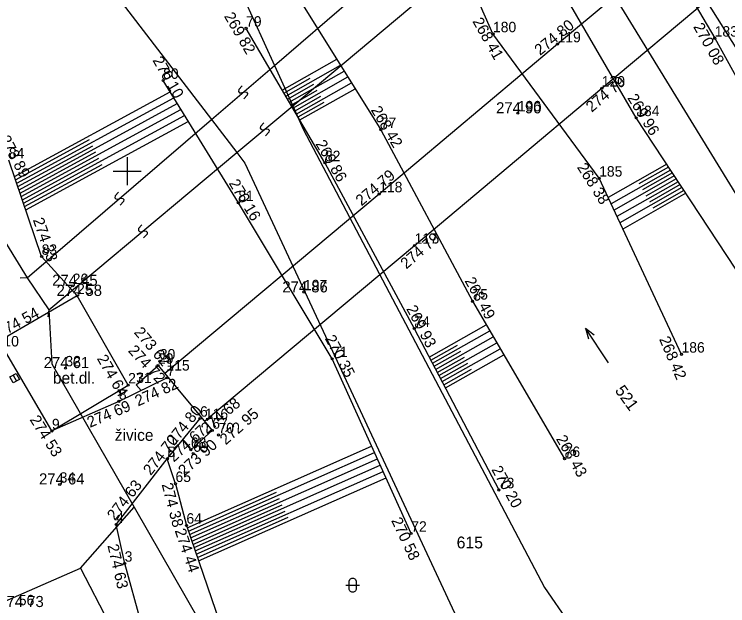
# Model space of a CAD drawing. Extents: x -492379 to -491966, y -1126153 to -1125860.
# Drawn here: x -492184.88 to -492154.06, y -1126038.78 to -1126013.22 of the extents above; entities that cross this region are included whole.
import ezdxf

# ---------------------------------------------------------------- set-up
doc = ezdxf.new("R2010")
doc.units = 0
for name, color, linetype in [('body', 7, 'Continuous'), ('hrana svahu', 7, 'Continuous'), ('kanalizace', 7, 'Continuous'), ('katastrální mapa', 7, 'Continuous'), ('ostatní objekty', 7, 'Continuous'), ('podrobný výškový bod', 7, 'Continuous'), ('popis ploch', 7, 'Continuous'), ('rozhraní ploch', 7, 'Continuous'), ('síť', 7, 'Continuous'), ('vodstvo', 7, 'Continuous'), ('výšky', 7, 'Continuous'), ('čísla bodů', 7, 'Continuous'), ('šrafy', 7, 'Continuous')]:
    doc.layers.add(name, color=color, linetype=linetype)

msp = doc.modelspace()

# ---------------------------------------------------------------- linework, layer by layer
at = {"layer": 'body'}
for p, q in [((-492174.865, -1126013.831), (-492174.865, -1126013.831)), ((-492164.201, -1126014.074), (-492164.201, -1126014.074)), ((-492154.625, -1126014.262), (-492154.625, -1126014.262)), ((-492161.411, -1126014.509), (-492161.411, -1126014.509)), ((-492178.448, -1126016.087), (-492178.448, -1126016.087)), ((-492159.503, -1126016.42), (-492159.503, -1126016.42)), ((-492163.128, -1126017.492), (-492163.128, -1126017.492)), ((-492158.013, -1126017.698), (-492158.013, -1126017.698)), ((-492169.047, -1126018.211), (-492169.047, -1126018.211)), ((-492171.458, -1126019.645), (-492171.458, -1126019.645)), ((-492159.615, -1126020.311), (-492159.615, -1126020.311)), ((-492169.116, -1126020.989), (-492169.116, -1126020.989)), ((-492175.199, -1126021.368), (-492175.199, -1126021.368)), ((-492167.589, -1126023.215), (-492167.589, -1126023.215)), ((-492183.695, -1126023.691), (-492183.695, -1126023.691)), ((-492182.354, -1126024.953), (-492182.354, -1126024.953)), ((-492172.363, -1126025.222), (-492172.363, -1126025.222)), ((-492182.164, -1126025.391), (-492182.164, -1126025.391)), ((-492165.087, -1126025.624), (-492165.087, -1126025.624)), ((-492167.599, -1126026.803), (-492167.599, -1126026.803)), ((-492171.148, -1126028.112), (-492171.148, -1126028.112)), ((-492156.058, -1126027.916), (-492156.058, -1126027.916)), ((-492178.667, -1126028.396), (-492178.667, -1126028.396)), ((-492178.591, -1126028.212), (-492178.591, -1126028.212)), ((-492182.668, -1126028.51), (-492182.668, -1126028.51)), ((-492178.305, -1126028.692), (-492178.305, -1126028.692)), ((-492178.279, -1126028.929), (-492178.279, -1126028.929)), ((-492179.957, -1126029.249), (-492179.957, -1126029.249)), ((-492179.61, -1126029.228), (-492179.61, -1126029.228)), ((-492180.359, -1126029.948), (-492180.359, -1126029.948)), ((-492176.853, -1126030.685), (-492176.853, -1126030.685)), ((-492176.644, -1126030.789), (-492176.644, -1126030.789)), ((-492176.325, -1126031.204), (-492176.325, -1126031.204)), ((-492183.251, -1126031.227), (-492183.251, -1126031.227)), ((-492176.057, -1126031.401), (-492176.057, -1126031.401)), ((-492177.249, -1126032.036), (-492177.249, -1126032.036)), ((-492178.267, -1126032.429), (-492178.267, -1126032.429)), ((-492177.149, -1126032.202), (-492177.149, -1126032.202)), ((-492161.105, -1126032.425), (-492161.105, -1126032.425)), ((-492182.916, -1126033.537), (-492182.916, -1126033.537)), ((-492177.915, -1126033.506), (-492177.915, -1126033.506)), ((-492163.945, -1126033.776), (-492163.945, -1126033.776)), ((-492180.477, -1126035.272), (-492180.477, -1126035.272)), ((-492177.441, -1126035.306), (-492177.441, -1126035.306)), ((-492167.73, -1126035.654), (-492167.73, -1126035.654)), ((-492180.108, -1126036.95), (-492180.108, -1126036.95))]:
    msp.add_line(p, q, dxfattribs=at)
at = {"layer": 'hrana svahu'}
for p, q in [((-492157.632, -1126009.099), (-492154.625, -1126014.262)), ((-492158.013, -1126017.698), (-492161.461, -1126011.771)), ((-492171.458, -1126019.645), (-492174.865, -1126013.831)), ((-492154.625, -1126014.262), (-492150.476, -1126021.763)), ((-492175.199, -1126021.368), (-492178.448, -1126016.087)), ((-492153.329, -1126024.834), (-492158.013, -1126017.698)), ((-492183.695, -1126023.691), (-492185.109, -1126019.52)), ((-492171.458, -1126019.645), (-492167.599, -1126026.803)), ((-492171.148, -1126028.112), (-492175.199, -1126021.368)), ((-492183.695, -1126023.691), (-492182.164, -1126025.391)), ((-492167.599, -1126026.803), (-492163.945, -1126033.776)), ((-492167.73, -1126035.654), (-492171.148, -1126028.112)), ((-492177.915, -1126033.506), (-492178.267, -1126032.429)), ((-492177.915, -1126033.506), (-492177.441, -1126035.306)), ((-492177.441, -1126035.306), (-492175.63, -1126040.598))]:
    msp.add_line(p, q, dxfattribs=at)
at = {"layer": 'kanalizace'}
msp.add_line((-492184.929, -1126028.814), (-492184.787, -1126029.078), dxfattribs=at)
msp.add_lwpolyline([(-492184.797, -1126028.743), (-492184.655, -1126029.008), (-492184.92, -1126029.149), (-492185.062, -1126028.885)], close=True, dxfattribs=at)
at = {"layer": 'katastrální mapa'}
for p, q in [((-492198.1, -1125989.34), (-492176.36, -1126017.77)), ((-492196.25, -1126005.33), (-492184.32, -1126024.61)), ((-492159.27, -1126005.79), (-492138.809, -1126038.508)), ((-492173.64, -1126015.43), (-492162.81, -1126006.12)), ((-492172.85, -1126017.18), (-492161.74, -1126007.87)), ((-492161.74, -1126007.87), (-492142.973, -1126038.587)), ((-492176.09, -1126010.03), (-492173.64, -1126015.43)), ((-492176.36, -1126017.77), (-492173.64, -1126015.43)), ((-492173.64, -1126015.43), (-492172.85, -1126017.18)), ((-492175.04, -1126016.32), (-492175.18, -1126016.48)), ((-492175.18, -1126016.48), (-492175.19, -1126016.56)), ((-492175.19, -1126016.56), (-492175.15, -1126016.61)), ((-492175.15, -1126016.61), (-492175.07, -1126016.62)), ((-492175.07, -1126016.62), (-492174.93, -1126016.58)), ((-492174.82, -1126016.72), (-492174.96, -1126016.88)), ((-492174.93, -1126016.58), (-492174.85, -1126016.59)), ((-492174.85, -1126016.59), (-492174.81, -1126016.64)), ((-492174.81, -1126016.64), (-492174.82, -1126016.72)), ((-492175.27, -1126019.2), (-492172.85, -1126017.18)), ((-492172.85, -1126017.18), (-492172.4, -1126018.18)), ((-492184.32, -1126024.61), (-492176.36, -1126017.77)), ((-492176.36, -1126017.77), (-492175.27, -1126019.2)), ((-492174.1, -1126017.91), (-492174.24, -1126018.07)), ((-492174.24, -1126018.07), (-492174.25, -1126018.15)), ((-492174.25, -1126018.15), (-492174.21, -1126018.2)), ((-492174.21, -1126018.2), (-492174.13, -1126018.21)), ((-492174.13, -1126018.21), (-492173.99, -1126018.17)), ((-492173.99, -1126018.17), (-492173.91, -1126018.18)), ((-492173.91, -1126018.18), (-492173.87, -1126018.23)), ((-492173.87, -1126018.23), (-492173.88, -1126018.31)), ((-492172.4, -1126018.18), (-492161.97, -1126037.99)), ((-492173.88, -1126018.31), (-492174.02, -1126018.47)), ((-492183.38, -1126026), (-492175.27, -1126019.2)), ((-492175.27, -1126019.2), (-492174.92, -1126019.66)), ((-492174.92, -1126019.66), (-492165.34, -1126040.21)), ((-492180.38, -1126020.91), (-492180.52, -1126021.07)), ((-492180.52, -1126021.07), (-492180.53, -1126021.15)), ((-492180.53, -1126021.15), (-492180.49, -1126021.2)), ((-492180.49, -1126021.2), (-492180.41, -1126021.21)), ((-492180.41, -1126021.21), (-492180.27, -1126021.17)), ((-492180.16, -1126021.31), (-492180.3, -1126021.47)), ((-492180.27, -1126021.17), (-492180.19, -1126021.18)), ((-492180.19, -1126021.18), (-492180.15, -1126021.23)), ((-492180.15, -1126021.23), (-492180.16, -1126021.31)), ((-492179.36, -1126022.32), (-492179.51, -1126022.48)), ((-492179.51, -1126022.48), (-492179.51, -1126022.56)), ((-492179.51, -1126022.56), (-492179.47, -1126022.61)), ((-492179.39, -1126022.62), (-492179.26, -1126022.58)), ((-492179.26, -1126022.58), (-492179.18, -1126022.59)), ((-492179.47, -1126022.61), (-492179.39, -1126022.62)), ((-492179.14, -1126022.72), (-492179.29, -1126022.88)), ((-492179.18, -1126022.59), (-492179.14, -1126022.64)), ((-492179.14, -1126022.64), (-492179.14, -1126022.72)), ((-492184.32, -1126024.61), (-492184.62, -1126024.63)), ((-492184.32, -1126024.61), (-492183.38, -1126026)), ((-492183.38, -1126026), (-492183.42, -1126026.29)), ((-492183.38, -1126026), (-492183.25, -1126028.33)), ((-492159.209, -1126028.283), (-492160.205, -1126026.785)), ((-492160.205, -1126026.785), (-492160.078, -1126027.242)), ((-492160.205, -1126026.785), (-492159.833, -1126027.077)), ((-492183.25, -1126028.33), (-492179.7, -1126034.52)), ((-492182.01, -1126037.16), (-492179.7, -1126034.52)), ((-492179.7, -1126034.52), (-492160.79, -1126067.45)), ((-492191.74, -1126041.4), (-492182.01, -1126037.16)), ((-492182.01, -1126037.16), (-492168.25, -1126063.67)), ((-492170.41, -1126037.71), (-492170.38, -1126037.65)), ((-492170.38, -1126037.65), (-492170.35, -1126037.62)), ((-492170.35, -1126037.62), (-492170.29, -1126037.59)), ((-492170.29, -1126037.59), (-492170.23, -1126037.59)), ((-492170.23, -1126037.59), (-492170.17, -1126037.62)), ((-492170.17, -1126037.62), (-492170.14, -1126037.65)), ((-492170.14, -1126037.65), (-492170.11, -1126037.71)), ((-492170.56, -1126037.89), (-492169.96, -1126037.89)), ((-492170.41, -1126038.07), (-492170.41, -1126037.71)), ((-492170.11, -1126037.71), (-492170.11, -1126038.07)), ((-492161.97, -1126037.99), (-492143.79, -1126064.46)), ((-492170.38, -1126038.13), (-492170.41, -1126038.07)), ((-492170.35, -1126038.16), (-492170.38, -1126038.13)), ((-492170.29, -1126038.19), (-492170.35, -1126038.16)), ((-492170.23, -1126038.19), (-492170.29, -1126038.19)), ((-492170.17, -1126038.16), (-492170.23, -1126038.19)), ((-492170.14, -1126038.13), (-492170.17, -1126038.16)), ((-492170.11, -1126038.07), (-492170.14, -1126038.13))]:
    msp.add_line(p, q, dxfattribs=at)
at = {"layer": 'ostatní objekty'}
for p, q in [((-492150.774, -1126005.547), (-492161.411, -1126014.509)), ((-492159.503, -1126016.42), (-492148.949, -1126007.574)), ((-492161.411, -1126014.509), (-492169.116, -1126020.989)), ((-492167.589, -1126023.215), (-492159.503, -1126016.42)), ((-492169.116, -1126020.989), (-492178.373, -1126028.749)), ((-492176.66, -1126030.802), (-492167.589, -1126023.215)), ((-492179.61, -1126029.228), (-492178.667, -1126028.396)), ((-492178.667, -1126028.396), (-492176.325, -1126031.204)), ((-492179.61, -1126029.228), (-492179.4, -1126029.478)), ((-492176.325, -1126031.204), (-492177.249, -1126032.036)), ((-492177.605, -1126031.613), (-492177.249, -1126032.036))]:
    msp.add_line(p, q, dxfattribs=at)
at = {"layer": 'podrobný výškový bod'}
for centre in [(-492174.865, -1126013.831), (-492164.201, -1126014.074), (-492154.625, -1126014.262), (-492161.411, -1126014.509), (-492178.448, -1126016.087), (-492159.503, -1126016.42), (-492163.128, -1126017.492), (-492158.013, -1126017.698), (-492169.047, -1126018.211), (-492171.458, -1126019.645), (-492159.615, -1126020.311), (-492169.116, -1126020.989), (-492175.199, -1126021.368), (-492167.589, -1126023.215), (-492183.695, -1126023.691), (-492182.354, -1126024.953), (-492182.164, -1126025.391), (-492172.363, -1126025.222), (-492165.087, -1126025.624), (-492167.599, -1126026.803), (-492171.148, -1126028.112), (-492156.058, -1126027.916), (-492178.667, -1126028.396), (-492178.591, -1126028.212), (-492182.668, -1126028.51), (-492178.279, -1126028.929), (-492179.957, -1126029.249), (-492180.359, -1126029.948), (-492176.853, -1126030.685), (-492183.251, -1126031.227), (-492176.325, -1126031.204), (-492176.057, -1126031.401), (-492177.249, -1126032.036), (-492178.267, -1126032.429), (-492177.149, -1126032.202), (-492161.105, -1126032.425), (-492182.916, -1126033.537), (-492177.915, -1126033.506), (-492163.945, -1126033.776), (-492180.477, -1126035.272), (-492177.441, -1126035.306), (-492167.73, -1126035.654), (-492180.108, -1126036.95)]:
    msp.add_circle(centre, 0.045, dxfattribs=at)
at = {"layer": 'rozhraní ploch'}
for p, q in [((-492182.164, -1126025.391), (-492185.549, -1126027.345)), ((-492179.957, -1126029.249), (-492182.164, -1126025.391)), ((-492183.251, -1126031.227), (-492185.346, -1126027.649)), ((-492178.279, -1126028.929), (-492180.359, -1126029.948)), ((-492183.251, -1126031.227), (-492179.957, -1126029.249)), ((-492180.359, -1126029.948), (-492183.251, -1126031.227)), ((-492178.267, -1126032.429), (-492176.853, -1126030.685)), ((-492180.477, -1126035.272), (-492178.267, -1126032.429)), ((-492180.108, -1126036.95), (-492180.477, -1126035.272)), ((-492179.273, -1126039.927), (-492180.108, -1126036.95))]:
    msp.add_line(p, q, dxfattribs=at)
at = {"layer": 'síť'}
for p, q in [((-492180, -1126019.4), (-492180, -1126020.6)), ((-492180.6, -1126020), (-492179.4, -1126020))]:
    msp.add_line(p, q, dxfattribs=at)
at = {"layer": 'vodstvo'}
for p, q in [((-492164.201, -1126014.074), (-492166.662, -1126008.473)), ((-492172.655, -1126012.43), (-492169.047, -1126018.211)), ((-492159.615, -1126020.311), (-492164.201, -1126014.074)), ((-492169.047, -1126018.211), (-492165.087, -1126025.624)), ((-492156.058, -1126027.916), (-492159.615, -1126020.311)), ((-492165.087, -1126025.624), (-492161.105, -1126032.425))]:
    msp.add_line(p, q, dxfattribs=at)
at = {"layer": 'šrafy'}
for p, q in [((-492173.303, -1126016.496), (-492170.948, -1126015.165)), ((-492173.152, -1126016.755), (-492170.789, -1126015.42)), ((-492173, -1126017.014), (-492170.63, -1126015.675)), ((-492173.227, -1126016.625), (-492172.093, -1126015.984)), ((-492172.848, -1126017.273), (-492170.471, -1126015.93)), ((-492173.076, -1126016.884), (-492171.941, -1126016.243)), ((-492172.697, -1126017.532), (-492170.312, -1126016.184)), ((-492184.868, -1126020.232), (-492178.149, -1126016.573)), ((-492172.924, -1126017.143), (-492171.79, -1126016.503)), ((-492172.545, -1126017.79), (-492170.153, -1126016.439)), ((-492184.77, -1126020.52), (-492177.992, -1126016.829)), ((-492172.772, -1126017.402), (-492171.639, -1126016.762)), ((-492172.621, -1126017.661), (-492171.488, -1126017.021)), ((-492184.672, -1126020.808), (-492177.834, -1126017.085)), ((-492184.575, -1126021.097), (-492177.677, -1126017.341)), ((-492184.477, -1126021.385), (-492177.519, -1126017.596)), ((-492184.379, -1126021.673), (-492177.362, -1126017.852)), ((-492184.819, -1126020.376), (-492181.624, -1126018.636)), ((-492184.721, -1126020.664), (-492181.489, -1126018.904)), ((-492184.623, -1126020.952), (-492181.354, -1126019.172)), ((-492184.526, -1126021.241), (-492181.219, -1126019.44)), ((-492184.428, -1126021.529), (-492181.084, -1126019.708)), ((-492156.698, -1126019.702), (-492159.228, -1126021.139)), ((-492156.533, -1126019.953), (-492159.1, -1126021.412)), ((-492156.615, -1126019.827), (-492157.894, -1126020.554)), ((-492156.45, -1126020.079), (-492157.745, -1126020.814)), ((-492156.368, -1126020.204), (-492158.973, -1126021.684)), ((-492156.285, -1126020.33), (-492157.596, -1126021.075)), ((-492156.203, -1126020.456), (-492158.845, -1126021.957)), ((-492156.038, -1126020.707), (-492158.718, -1126022.229)), ((-492156.12, -1126020.581), (-492157.447, -1126021.335)), ((-492155.873, -1126020.958), (-492158.59, -1126022.502)), ((-492155.955, -1126020.833), (-492157.298, -1126021.595)), ((-492166.955, -1126028.032), (-492164.492, -1126026.64)), ((-492166.816, -1126028.298), (-492164.34, -1126026.899)), ((-492166.676, -1126028.564), (-492164.189, -1126027.158)), ((-492166.885, -1126028.165), (-492165.735, -1126027.515)), ((-492166.537, -1126028.829), (-492164.037, -1126027.417)), ((-492166.746, -1126028.431), (-492165.583, -1126027.774)), ((-492166.398, -1126029.095), (-492163.886, -1126027.676)), ((-492166.607, -1126028.696), (-492165.432, -1126028.033)), ((-492166.258, -1126029.361), (-492163.734, -1126027.935)), ((-492166.467, -1126028.962), (-492165.281, -1126028.292)), ((-492166.328, -1126029.228), (-492165.13, -1126028.551)), ((-492177.404, -1126035.413), (-492169.441, -1126031.879)), ((-492177.307, -1126035.698), (-492169.317, -1126032.153)), ((-492177.209, -1126035.983), (-492169.193, -1126032.426)), ((-492177.112, -1126036.268), (-492169.069, -1126032.699)), ((-492177.014, -1126036.553), (-492168.945, -1126032.972)), ((-492176.917, -1126036.838), (-492168.821, -1126033.246)), ((-492177.356, -1126035.556), (-492173.549, -1126033.867)), ((-492177.258, -1126035.841), (-492173.424, -1126034.139)), ((-492177.161, -1126036.126), (-492173.299, -1126034.412)), ((-492177.063, -1126036.41), (-492173.174, -1126034.685)), ((-492176.966, -1126036.695), (-492173.049, -1126034.958))]:
    msp.add_line(p, q, dxfattribs=at)

# ---------------------------------------------------------------- texts
at = {"layer": 'katastrální mapa'}
msp.add_text('521', height=0.51, rotation=305.881, dxfattribs=at).set_placement((-492158.955, -1126029.482))
msp.add_text('615', height=0.51, dxfattribs=at).set_placement((-492165.77, -1126036.3))
at = {"layer": 'popis ploch'}
for s, p in [('bet.dl.', (-492183.207, -1126029.184)), ('živice', (-492180.536, -1126031.653))]:
    msp.add_text(s, height=0.5, dxfattribs=at).set_placement(p)
at = {"layer": 'výšky'}
for s, rotation, p in [('269 82', 300.2469, (-492175.83, -1126013.304)), ('268 41', 299.5607, (-492165.1, -1126013.528)), ('274 80', 39.5007, (-492162.166, -1126015.025)), ('270 08', 299.3475, (-492155.563, -1126013.759)), ('270 10', 299.9294, (-492178.919, -1126015.208)), ('274 79', 40.1281, (-492159.937, -1126017.48)), ('269 96', 301.3667, (-492158.41, -1126016.836)), ('268 42', 300.8153, (-492169.489, -1126017.357)), ('273 89', 298.1924, (-492185.522, -1126018.61)), ('269 86', 300.2536, (-492171.88, -1126018.821)), ('268 38', 302.1912, (-492160.585, -1126019.831)), ('274 79', 40.3826, (-492169.879, -1126021.528)), ('270 16', 301.1243, (-492175.625, -1126020.522)), ('274 33', 289.1415, (-492184.079, -1126022.104)), ('274 79', 40.713, (-492167.944, -1126024.254)), ('268 49', 298.7456, (-492165.437, -1126024.736)), ('274 54', 28.5451, (-492185.477, -1126027.214)), ('269 93', 297.7256, (-492167.958, -1126025.943)), ('273 62', 310.4177, (-492179.731, -1126026.978)), ('270 35', 297.864, (-492171.474, -1126027.229)), ('268 42', 293.1079, (-492157.032, -1126027.258)), ('274 72', 312.8933, (-492179.988, -1126027.78)), ('274 64', 299.5772, (-492181.322, -1126028.093)), ('274 82', 24.6497, (-492179.531, -1126030.172)), ('274 69', 23.1235, (-492181.607, -1126031.093)), ('274 68', 40.5539, (-492176.559, -1126031.381)), ('274 80', 51.1063, (-492177.972, -1126031.89)), ('272 95', 41.5117, (-492175.742, -1126031.853)), ('274 53', 302.2306, (-492184.227, -1126030.734)), ('274 67', 42.0009, (-492177.986, -1126032.596)), ('274 70', 51.5892, (-492178.981, -1126033.176)), ('268 43', 299.6467, (-492161.491, -1126031.567)), ('273 90', 41.689, (-492177.534, -1126033.2)), ('270 20', 298.9222, (-492164.28, -1126032.889)), ('274 63', 52.1283, (-492180.535, -1126035.127)), ('274 38', 284.753, (-492178.515, -1126033.534)), ('270 58', 295.3282, (-492168.607, -1126035.093)), ('274 44', 288.7897, (-492177.953, -1126035.53)), ('274 63', 283.1518, (-492180.855, -1126036.174))]:
    msp.add_text(s, height=0.48, rotation=rotation, dxfattribs=at).set_placement(p)
for s, p in [('274 90', (-492164.067, -1126017.504)), ('274 45', (-492183.24, -1126024.953)), ('274 58', (-492183.05, -1126025.391)), ('274 86', (-492173.299, -1126025.24)), ('274 61', (-492183.604, -1126028.51)), ('274 64', (-492183.807, -1126033.537)), ('274 73', (-492185.567, -1126038.835))]:
    msp.add_text(s, height=0.48, dxfattribs=at).set_placement(p)
at = {"layer": 'čísla bodů'}
for s, p in [('79', (-492174.865, -1126013.756)), ('180', (-492164.201, -1126013.999)), ('183', (-492154.625, -1126014.187)), ('119', (-492161.411, -1126014.434)), ('80', (-492178.448, -1126016.012)), ('120', (-492159.503, -1126016.345)), ('196', (-492163.128, -1126017.417)), ('184', (-492158.013, -1126017.623)), ('77', (-492169.047, -1126018.136)), ('84', (-492185.109, -1126019.445)), ('82', (-492171.458, -1126019.57)), ('185', (-492159.615, -1126020.236)), ('118', (-492169.116, -1126020.914)), ('81', (-492175.199, -1126021.293)), ('117', (-492167.589, -1126023.14)), ('83', (-492183.695, -1126023.616)), ('26', (-492182.354, -1126024.878)), ('197', (-492172.363, -1126025.147)), ('25', (-492182.164, -1126025.316)), ('75', (-492165.087, -1126025.549)), ('74', (-492167.599, -1126026.728)), ('10', (-492185.346, -1126027.574)), ('186', (-492156.058, -1126027.841)), ('30', (-492178.591, -1126028.137)), ('71', (-492171.148, -1126028.037)), ('32', (-492182.668, -1126028.435)), ('29', (-492178.667, -1126028.321)), ('115', (-492178.305, -1126028.617)), ('7', (-492178.279, -1126028.854)), ('27', (-492179.957, -1126029.174)), ('31', (-492179.61, -1126029.153)), ('8', (-492180.359, -1126029.873)), ('6', (-492176.853, -1126030.61)), ('116', (-492176.644, -1126030.714)), ('9', (-492183.251, -1126031.152)), ('67', (-492176.325, -1126031.129)), ('70', (-492176.057, -1126031.326)), ('68', (-492177.249, -1126031.961)), ('69', (-492177.149, -1126032.127)), ('5', (-492178.267, -1126032.354)), ('76', (-492161.105, -1126032.35)), ('34', (-492182.916, -1126033.462)), ('65', (-492177.915, -1126033.431)), ('73', (-492163.945, -1126033.701)), ('4', (-492180.477, -1126035.197)), ('64', (-492177.441, -1126035.231)), ('72', (-492167.73, -1126035.579)), ('3', (-492180.108, -1126036.875)), ('56', (-492184.681, -1126038.76))]:
    msp.add_text(s, height=0.45, dxfattribs=at).set_placement(p)

doc.saveas('drawing.dxf')
